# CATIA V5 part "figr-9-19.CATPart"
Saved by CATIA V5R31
Part number: Part3
Bounding box of the stored display mesh (mm): x -17.259 to 115.9, y -137.259 to 0, z -17.083 to 17.083
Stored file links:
  D:\PROJECTS\Project 2021\US EDITION\CATIA V5 6R 2021\Resources\Part Files\c09_catia_v5_6r2021_prt\c09_catia_v5_6r2021_prt\figr-9-19.CATPart
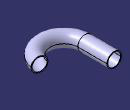
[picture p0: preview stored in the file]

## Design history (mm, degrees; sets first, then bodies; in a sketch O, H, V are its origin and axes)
Body1 (main body)
  Sketch1 on zx-plane, origin (0, 0, 0), H (-1, 0, 0), V (0, 0, 1)
    circle A1 centre (0, 0) radius 17.2586
  Sketch2 on xy-plane, origin (0, 0, 0), H (1, 0, 0), V (0, 1, 0)
    line L1 (0, 0) -> (0, -70)
    arc A1 centre (50, -70) radius 50 from (0, -70) to (50, -120) ccw
    arc A2 centre (50, -70) radius 50 from (50, -120) to (98.9898, -80) ccw
    vertical: L1 V
    tangency: A1 L1, A2 L1, A2 A1
  Rib1: profile Sketch1, centre curve Sketch2, thin wall 2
